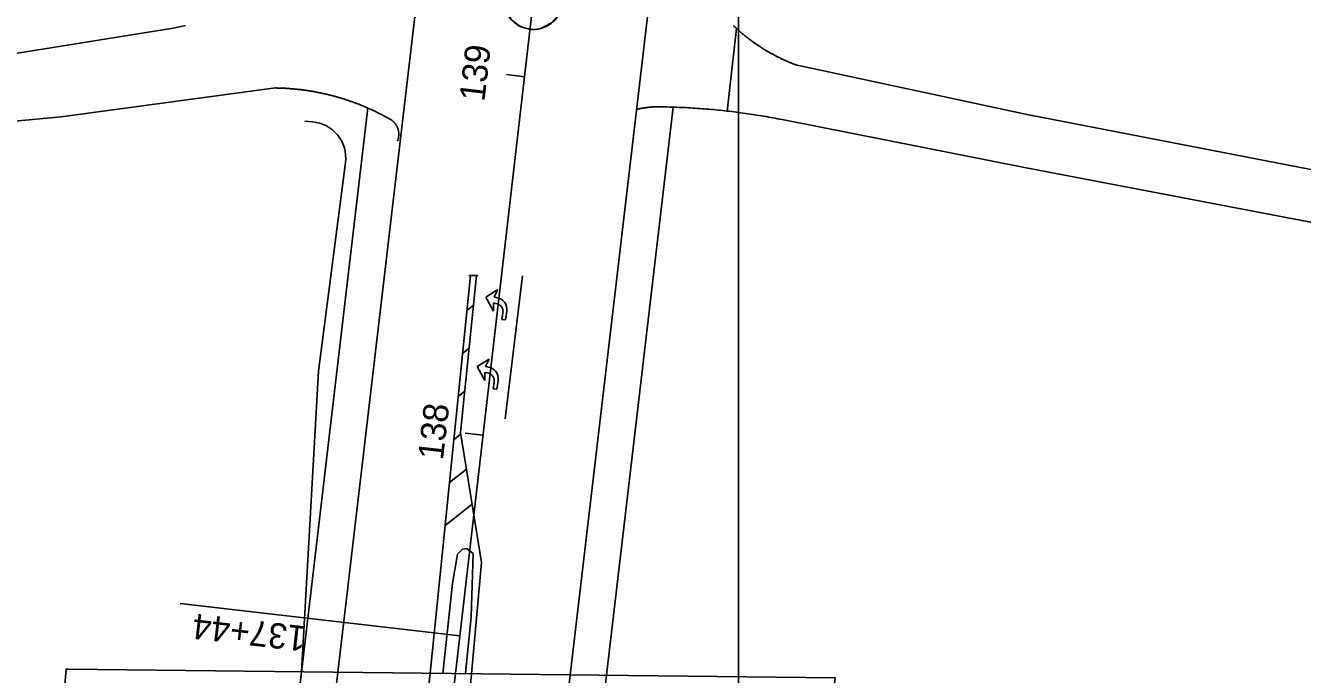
# Model space of a CAD drawing. Extents: x 2318076 to 2324211, y 613525 to 630327.
# Drawn here: x 2320472.4 to 2320826.1, y 628302.7 to 628482.6 of the extents above; entities that cross this region are included whole.
import ezdxf

# ---------------------------------------------------------------- set-up
doc = ezdxf.new("R2010")
doc.units = 0
for name, color, linetype in [('BR_X_Slab_Object', 7, 'Continuous'), ('GE_P_CL_50', 7, 'Continuous'), ('PM_P_Cells', 7, 'Continuous'), ('PM_P_Channelizing_Line', 7, 'Continuous'), ('PM_P_CL_Double_Solid', 7, 'Continuous'), ('PM_P_Island', 7, 'Continuous'), ('PM_P_Transverse_Line', 7, 'Continuous'), ('PM_X_CL_Double_Solid', 7, 'Continuous'), ('PV_P_EOP', 7, 'Continuous'), ('PV_P_Shoulder', 7, 'Continuous'), ('RD_X_Concrete_Barrier', 7, 'Continuous'), ('RD_X_GR_Lt', 7, 'Continuous'), ('RS_Raster1', 7, 'Continuous'), ('SC_Scratch3', 7, 'Continuous')]:
    doc.layers.add(name, color=color, linetype=linetype)

msp = doc.modelspace()

# ---------------------------------------------------------------- linework, layer by layer
at = {"layer": 'BR_X_Slab_Object'}
msp.add_lwpolyline([(2320484.11, 628304.16), (2320696.64, 628301.84), (2320691.49, 628259.41), (2320480.05, 628262.45), (2320483.63, 628304.22), (2320484.11, 628304.16)], dxfattribs=at)
at = {"layer": 'GE_P_CL_50'}
for p, q in [((2320610.64, 628468.38), (2320605.67, 628468.95)), ((2320599.16, 628369.04), (2320594.19, 628369.61)), ((2320592.73, 628313.41), (2320515.25, 628322.36))]:
    msp.add_line(p, q, dxfattribs=at)
msp.add_lwpolyline([(2320476.3, 627307.7), (2320485.22, 627375.57), (2320502.11, 627520.92), (2320519.22, 627676.47), (2320531.82, 627783.89), (2320546.8, 627927.12), (2320554.45, 627991.34), (2320572.51, 628138.41), (2320649.52, 628804.84), (2320678.77, 629064.5), (2320690.76, 629163.78), (2320713.75, 629362.45), (2320725.26, 629461.78), (2320736.97, 629561.09), (2320748.4, 629660.43), (2320759.09, 629759.86), (2320769.62, 629859.3), (2320777.51, 629931.12), (2320778.25, 629937.84)], dxfattribs=at)
at = {"layer": 'PM_P_Cells'}
for p, q in [((2320603.22, 628409.38), (2320599.87, 628407.29)), ((2320602.23, 628407.26), (2320603.22, 628409.38)), ((2320603.22, 628409.38), (2320603.22, 628409.38)), ((2320599.87, 628407.29), (2320601.99, 628403.41)), ((2320602.89, 628407.16), (2320602.23, 628407.26)), ((2320601.99, 628403.41), (2320601.99, 628405.68)), ((2320601.99, 628405.68), (2320602.69, 628405.57)), ((2320604.62, 628402.96), (2320604.35, 628401.12)), ((2320605.34, 628400.97), (2320605.7, 628403.43)), ((2320602.04, 628401.46), (2320602.04, 628401.46)), ((2320604.35, 628401.12), (2320605.34, 628400.97)), ((2320600.8, 628390.15), (2320597.46, 628388.06)), ((2320599.81, 628388.04), (2320600.8, 628390.15)), ((2320600.8, 628390.15), (2320600.8, 628390.15)), ((2320597.46, 628388.06), (2320599.58, 628384.19)), ((2320599.58, 628384.19), (2320599.58, 628386.45)), ((2320599.58, 628386.45), (2320600.27, 628386.35)), ((2320600.47, 628387.94), (2320599.81, 628388.04)), ((2320599.63, 628382.24), (2320599.63, 628382.24)), ((2320602.21, 628383.74), (2320601.93, 628381.9)), ((2320601.93, 628381.9), (2320602.92, 628381.75)), ((2320602.92, 628381.75), (2320603.29, 628384.2))]:
    msp.add_line(p, q, dxfattribs=at)
for centre, radius, end in [((2320602.46, 628403.91), 3.28, 82.4632), ((2320602.35, 628403.3), 2.3, 81.5547), ((2320599.94, 628384.08), 2.3, 81.5547), ((2320600.04, 628384.68), 3.28, 82.4632)]:
    msp.add_arc(centre, radius, 351.5547, end, dxfattribs=at)
at = {"layer": 'PM_P_Channelizing_Line'}
msp.add_lwpolyline([(2320605.23, 628373.54), (2320610.1, 628413.2)], dxfattribs=at)
at = {"layer": 'PM_P_CL_Double_Solid'}
for p, q in [((2320584.51, 628303.06), (2320595.7, 628413.25)), ((2320592.91, 628369.76), (2320597.33, 628413.25)), ((2320592.91, 628369.76), (2320598.66, 628333.76)), ((2320598.66, 628333.76), (2320595.94, 628302.94))]:
    msp.add_line(p, q, dxfattribs=at)
at = {"layer": 'PM_P_Island'}
msp.add_lwpolyline([(2320622.04, 628497.59), (2320606, 628499.42), (2320604.93, 628490.08), (2320605.45, 628486.7), (2320606.99, 628484.17), (2320609.45, 628482.31), (2320611.9, 628481.55), (2320612.52, 628481.49), (2320613.49, 628481.49), (2320615.17, 628481.76), (2320618.12, 628483.27), (2320620.03, 628485.47), (2320620.95, 628487.79)], close=True, dxfattribs=at)
at = {"layer": 'PM_P_Transverse_Line'}
for p, q in [((2320596.5, 628405.08), (2320594.73, 628403.68)), ((2320595.29, 628393.15), (2320593.52, 628391.75)), ((2320594.07, 628381.22), (2320592.31, 628379.82)), ((2320592.97, 628369.38), (2320591.09, 628367.89)), ((2320594.53, 628359.64), (2320589.88, 628355.96)), ((2320596.08, 628349.9), (2320588.67, 628344.03))]:
    msp.add_line(p, q, dxfattribs=at)
at = {"layer": 'PM_X_CL_Double_Solid'}
msp.add_line((2320595.15, 628413.25), (2320597.78, 628413.25), dxfattribs=at)
at = {"layer": 'PV_P_EOP'}
for p, q in [((2320590.74, 628574.92), (2320513.05, 627912.02)), ((2320576.7, 627905.37), (2320654.32, 628567.57)), ((2320666.71, 628458.87), (2320669.35, 628481.73)), ((2320584.51, 628303.06), (2320566.09, 628143.74)), ((2320595.94, 628302.94), (2320581.17, 628143.24))]:
    msp.add_line(p, q, dxfattribs=at)
for points in [[(2320668.46, 628482.56), (2320668.59, 628482.43), (2320668.72, 628482.31), (2320668.85, 628482.19), (2320668.99, 628482.06), (2320669.35, 628481.73)], [(2320649.48, 628460), (2320649.4, 628460), (2320649.31, 628460.01), (2320649.23, 628460.01), (2320649.15, 628460.02), (2320649.07, 628460.02), (2320648.98, 628460.02), (2320648.9, 628460.03), (2320648.82, 628460.03), (2320648.74, 628460.03), (2320648.65, 628460.04), (2320648.57, 628460.04), (2320648.49, 628460.04), (2320648.4, 628460.04), (2320648.32, 628460.04), (2320648.24, 628460.04), (2320648.15, 628460.05), (2320648.07, 628460.05), (2320647.99, 628460.05), (2320647.91, 628460.05), (2320647.82, 628460.05), (2320647.74, 628460.05), (2320647.66, 628460.05), (2320647.57, 628460.04), (2320647.49, 628460.04), (2320647.41, 628460.04), (2320647.32, 628460.04), (2320647.24, 628460.04), (2320647.16, 628460.04), (2320647.08, 628460.03), (2320646.99, 628460.03), (2320646.91, 628460.03), (2320646.83, 628460.03), (2320646.74, 628460.02), (2320646.66, 628460.02), (2320646.58, 628460.01), (2320646.49, 628460.01), (2320646.41, 628460.01), (2320646.33, 628460), (2320646.25, 628460), (2320646.16, 628459.99), (2320646.08, 628459.99), (2320646, 628459.98), (2320645.91, 628459.97), (2320645.83, 628459.97), (2320645.75, 628459.96), (2320645.66, 628459.95), (2320645.58, 628459.95), (2320645.5, 628459.94), (2320645.42, 628459.93), (2320645.33, 628459.93), (2320645.25, 628459.92), (2320645.17, 628459.91), (2320645.09, 628459.9), (2320645, 628459.89), (2320644.92, 628459.88), (2320644.84, 628459.87), (2320644.75, 628459.86), (2320644.67, 628459.85), (2320644.59, 628459.84), (2320644.51, 628459.83), (2320644.42, 628459.82), (2320644.34, 628459.81), (2320644.26, 628459.8), (2320644.18, 628459.79), (2320644.1, 628459.78), (2320644.01, 628459.77), (2320643.93, 628459.76), (2320643.85, 628459.74), (2320643.77, 628459.73), (2320643.68, 628459.72), (2320643.6, 628459.71), (2320643.52, 628459.69), (2320643.44, 628459.68), (2320643.36, 628459.66), (2320643.27, 628459.65), (2320643.19, 628459.64), (2320643.11, 628459.62), (2320643.03, 628459.61), (2320642.95, 628459.59), (2320642.87, 628459.58), (2320642.78, 628459.56), (2320642.7, 628459.55), (2320642.62, 628459.53), (2320642.54, 628459.51), (2320642.46, 628459.5), (2320642.38, 628459.48), (2320642.3, 628459.46), (2320642.22, 628459.45), (2320641.63, 628459.32)], [(2320666.71, 628458.87), (2320664.83, 628459.07), (2320664.19, 628459.13), (2320663.56, 628459.19), (2320662.92, 628459.25), (2320662.28, 628459.31), (2320661.64, 628459.37), (2320661, 628459.42), (2320660.36, 628459.47), (2320659.72, 628459.52), (2320659.08, 628459.57), (2320658.44, 628459.61), (2320657.81, 628459.65), (2320657.17, 628459.69), (2320656.53, 628459.73), (2320655.89, 628459.77), (2320655.25, 628459.8), (2320654.61, 628459.83), (2320653.96, 628459.86), (2320653.32, 628459.89), (2320652.68, 628459.91), (2320652.04, 628459.93), (2320651.4, 628459.95), (2320650.76, 628459.97), (2320650.12, 628459.99), (2320649.48, 628460)]]:
    msp.add_lwpolyline(points, dxfattribs=at)
msp.add_arc((2320613.03, 628489.59), 8.12, 175.7115, 350.2041, dxfattribs=at)
at = {"layer": 'PV_P_Shoulder'}
for p, q in [((2320567.18, 628459.79), (2320515.22, 628016.39)), ((2320599.22, 628011.62), (2320651.77, 628459.98))]:
    msp.add_line(p, q, dxfattribs=at)
at = {"layer": 'RD_X_Concrete_Barrier'}
msp.add_line((2320532.74, 628165.9), (2320548.86, 628303.45), dxfattribs=at)
msp.add_lwpolyline([(2320588, 628303.03), (2320590.67, 628327.94), (2320592.06, 628336.09), (2320593.44, 628337.44), (2320594.67, 628337.67), (2320596.35, 628336.22), (2320595.82, 628318.82), (2320594.3, 628302.96)], dxfattribs=at)
at = {"layer": 'RD_X_GR_Lt'}
for p, q in [((2320549.79, 628456.05), (2320551.93, 628455.87)), ((2320553.6, 628386.82), (2320561.02, 628444.63)), ((2320548.86, 628303.45), (2320553.6, 628386.82))]:
    msp.add_line(p, q, dxfattribs=at)
msp.add_arc((2320551.1, 628445.9), 10, 352.6854, 85.2335, dxfattribs=at)
at = {"layer": 'RS_Raster1'}
for p, q in [((2320429.11, 628468.24), (2320513.35, 628481.85)), ((2320686.14, 628471.54), (2320751.52, 628457.58)), ((2320749.08, 628443.19), (2320681.94, 628456.49)), ((2320872.26, 628434.14), (2320750.75, 628457.74)), ((2320902.18, 628413.99), (2320749.08, 628443.19))]:
    msp.add_line(p, q, dxfattribs=at)
for points in [[(2320513.35, 628481.85), (2320513.78, 628481.94), (2320514.2, 628482.03), (2320514.63, 628482.12), (2320515.05, 628482.21), (2320515.48, 628482.3), (2320515.9, 628482.39), (2320516.33, 628482.49), (2320516.75, 628482.58)], [(2320668.46, 628482.56), (2320668.59, 628482.43), (2320668.72, 628482.31), (2320668.85, 628482.19), (2320668.99, 628482.06), (2320669.12, 628481.94), (2320669.25, 628481.82), (2320669.38, 628481.69), (2320669.52, 628481.57), (2320669.65, 628481.45), (2320669.79, 628481.33), (2320669.92, 628481.21), (2320670.06, 628481.09), (2320670.19, 628480.97), (2320670.33, 628480.85), (2320670.47, 628480.73), (2320670.6, 628480.62), (2320670.74, 628480.5), (2320670.88, 628480.38), (2320671.02, 628480.27), (2320671.16, 628480.15), (2320671.3, 628480.04), (2320671.44, 628479.92), (2320671.58, 628479.81), (2320671.72, 628479.69), (2320671.86, 628479.58), (2320672, 628479.47), (2320672.14, 628479.35), (2320672.28, 628479.24), (2320672.42, 628479.13), (2320672.57, 628479.02), (2320672.71, 628478.91), (2320672.85, 628478.8), (2320673, 628478.69), (2320673.14, 628478.58), (2320673.29, 628478.47), (2320673.43, 628478.37), (2320673.58, 628478.26), (2320673.73, 628478.15), (2320673.87, 628478.05), (2320674.02, 628477.94), (2320674.17, 628477.83), (2320674.31, 628477.73), (2320674.46, 628477.63), (2320674.61, 628477.52), (2320674.76, 628477.42), (2320674.91, 628477.32), (2320675.06, 628477.21), (2320675.21, 628477.11), (2320675.36, 628477.01), (2320675.51, 628476.91), (2320675.66, 628476.81), (2320675.81, 628476.71), (2320675.96, 628476.61), (2320676.11, 628476.52), (2320676.27, 628476.42), (2320676.42, 628476.32), (2320676.57, 628476.23), (2320676.72, 628476.13), (2320676.88, 628476.03), (2320677.03, 628475.94), (2320677.19, 628475.84), (2320677.34, 628475.75), (2320677.5, 628475.66), (2320677.65, 628475.57), (2320677.81, 628475.47), (2320677.96, 628475.38), (2320678.12, 628475.29), (2320678.28, 628475.2), (2320678.43, 628475.11), (2320678.59, 628475.02), (2320678.75, 628474.93), (2320678.91, 628474.84), (2320679.07, 628474.76), (2320679.22, 628474.67), (2320679.38, 628474.58), (2320679.54, 628474.5), (2320679.7, 628474.41), (2320679.86, 628474.33), (2320680.02, 628474.24), (2320680.18, 628474.16), (2320680.34, 628474.08), (2320680.5, 628473.99), (2320680.66, 628473.91), (2320680.83, 628473.83), (2320680.99, 628473.75), (2320681.15, 628473.67), (2320681.31, 628473.59), (2320681.48, 628473.51), (2320681.64, 628473.43), (2320681.8, 628473.35), (2320681.97, 628473.28), (2320682.13, 628473.2), (2320682.29, 628473.12), (2320682.46, 628473.05), (2320682.62, 628472.97), (2320682.79, 628472.9), (2320682.95, 628472.83), (2320683.12, 628472.75), (2320683.28, 628472.68), (2320683.45, 628472.61), (2320683.62, 628472.54), (2320683.78, 628472.47), (2320683.95, 628472.4), (2320684.12, 628472.33), (2320684.28, 628472.26), (2320684.45, 628472.19), (2320684.62, 628472.12), (2320684.79, 628472.06), (2320684.96, 628471.99), (2320685.12, 628471.92), (2320685.29, 628471.86), (2320685.46, 628471.79), (2320685.63, 628471.73), (2320685.8, 628471.67), (2320685.97, 628471.6), (2320686.14, 628471.54)], [(2320541.61, 628465.25), (2320482.26, 628457.22), (2320418.88, 628451.31), (2320347.06, 628441.39), (2320257.15, 628427.56), (2320159.66, 628413.29), (2320059.39, 628398.63), (2319964.41, 628383.7), (2319830.88, 628363.16), (2319830.71, 628363.13), (2319830.71, 628363.13)], [(2320573.86, 628456.31), (2320573.66, 628456.43), (2320573.46, 628456.54), (2320573.26, 628456.66), (2320573.06, 628456.77), (2320572.85, 628456.88), (2320572.65, 628457), (2320572.45, 628457.11), (2320572.25, 628457.22), (2320572.04, 628457.33), (2320571.84, 628457.44), (2320571.63, 628457.55), (2320571.43, 628457.66), (2320571.22, 628457.77), (2320571.02, 628457.87), (2320570.81, 628457.98), (2320570.61, 628458.09), (2320570.4, 628458.19), (2320570.19, 628458.3), (2320569.98, 628458.4), (2320569.78, 628458.5), (2320569.57, 628458.6), (2320569.36, 628458.71), (2320569.15, 628458.81), (2320568.94, 628458.91), (2320568.73, 628459), (2320568.52, 628459.1), (2320568.31, 628459.2), (2320568.1, 628459.3), (2320567.89, 628459.39), (2320567.68, 628459.49), (2320567.47, 628459.58), (2320567.26, 628459.68), (2320567.04, 628459.77), (2320566.83, 628459.86), (2320566.62, 628459.95), (2320566.41, 628460.05), (2320566.19, 628460.14), (2320565.98, 628460.22), (2320565.76, 628460.31), (2320565.55, 628460.4), (2320565.33, 628460.49), (2320565.12, 628460.57), (2320564.9, 628460.66), (2320564.69, 628460.74), (2320564.47, 628460.83), (2320564.26, 628460.91), (2320564.04, 628460.99), (2320563.82, 628461.08), (2320563.61, 628461.16), (2320563.39, 628461.24), (2320563.17, 628461.32), (2320562.95, 628461.4), (2320562.73, 628461.47), (2320562.51, 628461.55), (2320562.3, 628461.63), (2320562.08, 628461.7), (2320561.86, 628461.78), (2320561.64, 628461.85), (2320561.42, 628461.92), (2320561.2, 628462), (2320560.98, 628462.07), (2320560.76, 628462.14), (2320560.54, 628462.21), (2320560.31, 628462.28), (2320560.09, 628462.35), (2320559.87, 628462.42), (2320559.65, 628462.48), (2320559.43, 628462.55), (2320559.21, 628462.61), (2320558.98, 628462.68), (2320558.76, 628462.74), (2320558.54, 628462.81), (2320558.31, 628462.87), (2320558.09, 628462.93), (2320557.87, 628462.99), (2320557.64, 628463.05), (2320557.42, 628463.11), (2320557.19, 628463.17), (2320556.97, 628463.23), (2320556.75, 628463.28), (2320556.52, 628463.34), (2320556.3, 628463.39), (2320556.07, 628463.45), (2320555.84, 628463.5), (2320555.62, 628463.55), (2320555.39, 628463.61), (2320555.17, 628463.66), (2320554.94, 628463.71), (2320554.71, 628463.76), (2320554.49, 628463.81), (2320554.26, 628463.85), (2320554.03, 628463.9), (2320553.81, 628463.95), (2320553.58, 628463.99), (2320553.35, 628464.04), (2320553.12, 628464.08), (2320552.9, 628464.13), (2320552.67, 628464.17), (2320552.44, 628464.21), (2320552.21, 628464.25), (2320551.98, 628464.29), (2320551.76, 628464.33), (2320551.53, 628464.37), (2320551.3, 628464.41), (2320551.07, 628464.44), (2320550.84, 628464.48), (2320550.61, 628464.51), (2320550.38, 628464.55), (2320550.15, 628464.58), (2320549.92, 628464.61), (2320549.69, 628464.65), (2320549.46, 628464.68), (2320549.23, 628464.71), (2320549.01, 628464.74), (2320548.78, 628464.77), (2320548.54, 628464.79), (2320548.31, 628464.82), (2320548.08, 628464.85), (2320547.85, 628464.87), (2320547.62, 628464.9), (2320547.39, 628464.92), (2320547.16, 628464.94), (2320546.93, 628464.97), (2320546.7, 628464.99), (2320546.47, 628465.01), (2320546.24, 628465.03), (2320546.01, 628465.05), (2320545.78, 628465.06), (2320545.55, 628465.08), (2320545.31, 628465.1), (2320545.08, 628465.11), (2320544.85, 628465.13), (2320544.62, 628465.14), (2320544.39, 628465.16), (2320544.16, 628465.17), (2320543.93, 628465.18), (2320543.7, 628465.19), (2320543.46, 628465.2), (2320543.23, 628465.21), (2320543, 628465.22), (2320542.77, 628465.22), (2320542.54, 628465.23), (2320542.31, 628465.24), (2320542.07, 628465.24), (2320541.84, 628465.25), (2320541.61, 628465.25)], [(2320649.48, 628460), (2320649.4, 628460), (2320649.31, 628460.01), (2320649.23, 628460.01), (2320649.15, 628460.02), (2320649.07, 628460.02), (2320648.98, 628460.02), (2320648.9, 628460.03), (2320648.82, 628460.03), (2320648.74, 628460.03), (2320648.65, 628460.04), (2320648.57, 628460.04), (2320648.49, 628460.04), (2320648.4, 628460.04), (2320648.32, 628460.04), (2320648.24, 628460.04), (2320648.15, 628460.05), (2320648.07, 628460.05), (2320647.99, 628460.05), (2320647.91, 628460.05), (2320647.82, 628460.05), (2320647.74, 628460.05), (2320647.66, 628460.05), (2320647.57, 628460.04), (2320647.49, 628460.04), (2320647.41, 628460.04), (2320647.32, 628460.04), (2320647.24, 628460.04), (2320647.16, 628460.04), (2320647.08, 628460.03), (2320646.99, 628460.03), (2320646.91, 628460.03), (2320646.83, 628460.03), (2320646.74, 628460.02), (2320646.66, 628460.02), (2320646.58, 628460.01), (2320646.49, 628460.01), (2320646.41, 628460.01), (2320646.33, 628460), (2320646.25, 628460), (2320646.16, 628459.99), (2320646.08, 628459.99), (2320646, 628459.98), (2320645.91, 628459.97), (2320645.83, 628459.97), (2320645.75, 628459.96), (2320645.66, 628459.95), (2320645.58, 628459.95), (2320645.5, 628459.94), (2320645.42, 628459.93), (2320645.33, 628459.93), (2320645.25, 628459.92), (2320645.17, 628459.91), (2320645.09, 628459.9), (2320645, 628459.89), (2320644.92, 628459.88), (2320644.84, 628459.87), (2320644.75, 628459.86), (2320644.67, 628459.85), (2320644.59, 628459.84), (2320644.51, 628459.83), (2320644.42, 628459.82), (2320644.34, 628459.81), (2320644.26, 628459.8), (2320644.18, 628459.79), (2320644.1, 628459.78), (2320644.01, 628459.77), (2320643.93, 628459.76), (2320643.85, 628459.74), (2320643.77, 628459.73), (2320643.68, 628459.72), (2320643.6, 628459.71), (2320643.52, 628459.69), (2320643.44, 628459.68), (2320643.36, 628459.66), (2320643.27, 628459.65), (2320643.19, 628459.64), (2320643.11, 628459.62), (2320643.03, 628459.61), (2320642.95, 628459.59), (2320642.87, 628459.58), (2320642.78, 628459.56), (2320642.7, 628459.55), (2320642.62, 628459.53), (2320642.54, 628459.51), (2320642.46, 628459.5), (2320642.38, 628459.48), (2320642.3, 628459.46), (2320642.22, 628459.45), (2320641.81, 628459.36)], [(2320681.94, 628456.49), (2320681.31, 628456.61), (2320680.68, 628456.74), (2320680.05, 628456.86), (2320679.42, 628456.97), (2320678.79, 628457.09), (2320678.16, 628457.2), (2320677.53, 628457.31), (2320676.9, 628457.42), (2320676.27, 628457.53), (2320675.63, 628457.63), (2320675, 628457.73), (2320674.37, 628457.83), (2320673.73, 628457.93), (2320673.1, 628458.03), (2320672.46, 628458.12), (2320671.83, 628458.21), (2320671.2, 628458.3), (2320670.56, 628458.39), (2320669.92, 628458.47), (2320669.29, 628458.55), (2320668.65, 628458.63), (2320668.02, 628458.71), (2320667.38, 628458.79), (2320666.74, 628458.86), (2320666.11, 628458.93), (2320665.47, 628459), (2320664.83, 628459.07), (2320664.19, 628459.13), (2320663.56, 628459.19), (2320662.92, 628459.25), (2320662.28, 628459.31), (2320661.64, 628459.37), (2320661, 628459.42), (2320660.36, 628459.47), (2320659.72, 628459.52), (2320659.08, 628459.57), (2320658.44, 628459.61), (2320657.81, 628459.65), (2320657.17, 628459.69), (2320656.53, 628459.73), (2320655.89, 628459.77), (2320655.25, 628459.8), (2320654.61, 628459.83), (2320653.96, 628459.86), (2320653.32, 628459.89), (2320652.68, 628459.91), (2320652.04, 628459.93), (2320651.4, 628459.95), (2320650.76, 628459.97), (2320650.12, 628459.99), (2320649.48, 628460)], [(2320575.44, 628450.58), (2320575.47, 628450.66), (2320575.5, 628450.74), (2320575.53, 628450.82), (2320575.56, 628450.9), (2320575.58, 628450.98), (2320575.61, 628451.06), (2320575.63, 628451.14), (2320575.65, 628451.22), (2320575.67, 628451.3), (2320575.69, 628451.38), (2320575.71, 628451.46), (2320575.72, 628451.55), (2320575.74, 628451.63), (2320575.75, 628451.71), (2320575.76, 628451.8), (2320575.77, 628451.88), (2320575.78, 628451.96), (2320575.79, 628452.05), (2320575.79, 628452.13), (2320575.8, 628452.22), (2320575.8, 628452.3), (2320575.8, 628452.38), (2320575.8, 628452.47), (2320575.8, 628452.55), (2320575.79, 628452.64), (2320575.79, 628452.72), (2320575.78, 628452.8), (2320575.78, 628452.89), (2320575.77, 628452.97), (2320575.76, 628453.05), (2320575.75, 628453.14), (2320575.73, 628453.22), (2320575.72, 628453.3), (2320575.7, 628453.39), (2320575.69, 628453.47), (2320575.67, 628453.55), (2320575.65, 628453.63), (2320575.62, 628453.71), (2320575.6, 628453.79), (2320575.58, 628453.87), (2320575.55, 628453.96), (2320575.52, 628454.03), (2320575.5, 628454.11), (2320575.47, 628454.19), (2320575.43, 628454.27), (2320575.4, 628454.35), (2320575.37, 628454.42), (2320575.33, 628454.5), (2320575.3, 628454.58), (2320575.26, 628454.65), (2320575.22, 628454.73), (2320575.18, 628454.8), (2320575.14, 628454.87), (2320575.09, 628454.95), (2320575.05, 628455.02), (2320575, 628455.09), (2320574.96, 628455.16), (2320574.91, 628455.23), (2320574.86, 628455.3), (2320574.81, 628455.36), (2320574.76, 628455.43), (2320574.71, 628455.49), (2320574.65, 628455.56), (2320574.6, 628455.62), (2320574.54, 628455.69), (2320574.48, 628455.75), (2320574.43, 628455.81), (2320574.37, 628455.87), (2320574.31, 628455.93), (2320574.25, 628455.99), (2320574.18, 628456.04), (2320574.12, 628456.1), (2320574.06, 628456.15), (2320573.99, 628456.21), (2320573.93, 628456.26), (2320573.86, 628456.31)]]:
    msp.add_lwpolyline(points, dxfattribs=at)
at = {"layer": 'SC_Scratch3'}
msp.add_line((2320669.87, 614778.41), (2320669.87, 630327.22), dxfattribs=at)

# ---------------------------------------------------------------- texts
at = {"layer": 'GE_P_CL_50'}
for s, rotation, p in [('139', 83.4084, (2320599.5, 628461.31)), ('138', 83.4084, (2320588.02, 628361.94)), ('137+44', 173.4084, (2320550.44, 628316.01))]:
    msp.add_text(s, height=7, rotation=rotation, dxfattribs=at).set_placement(p)

doc.saveas('drawing.dxf')
